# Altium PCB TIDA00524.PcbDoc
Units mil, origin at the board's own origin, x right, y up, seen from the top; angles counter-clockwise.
Board outline 2335 x 1723 mil, 2 copper layers (Top Layer, Bottom Layer), stack 62 mil thick; 54 components, 27 nets, 173 pads, 59 vias.
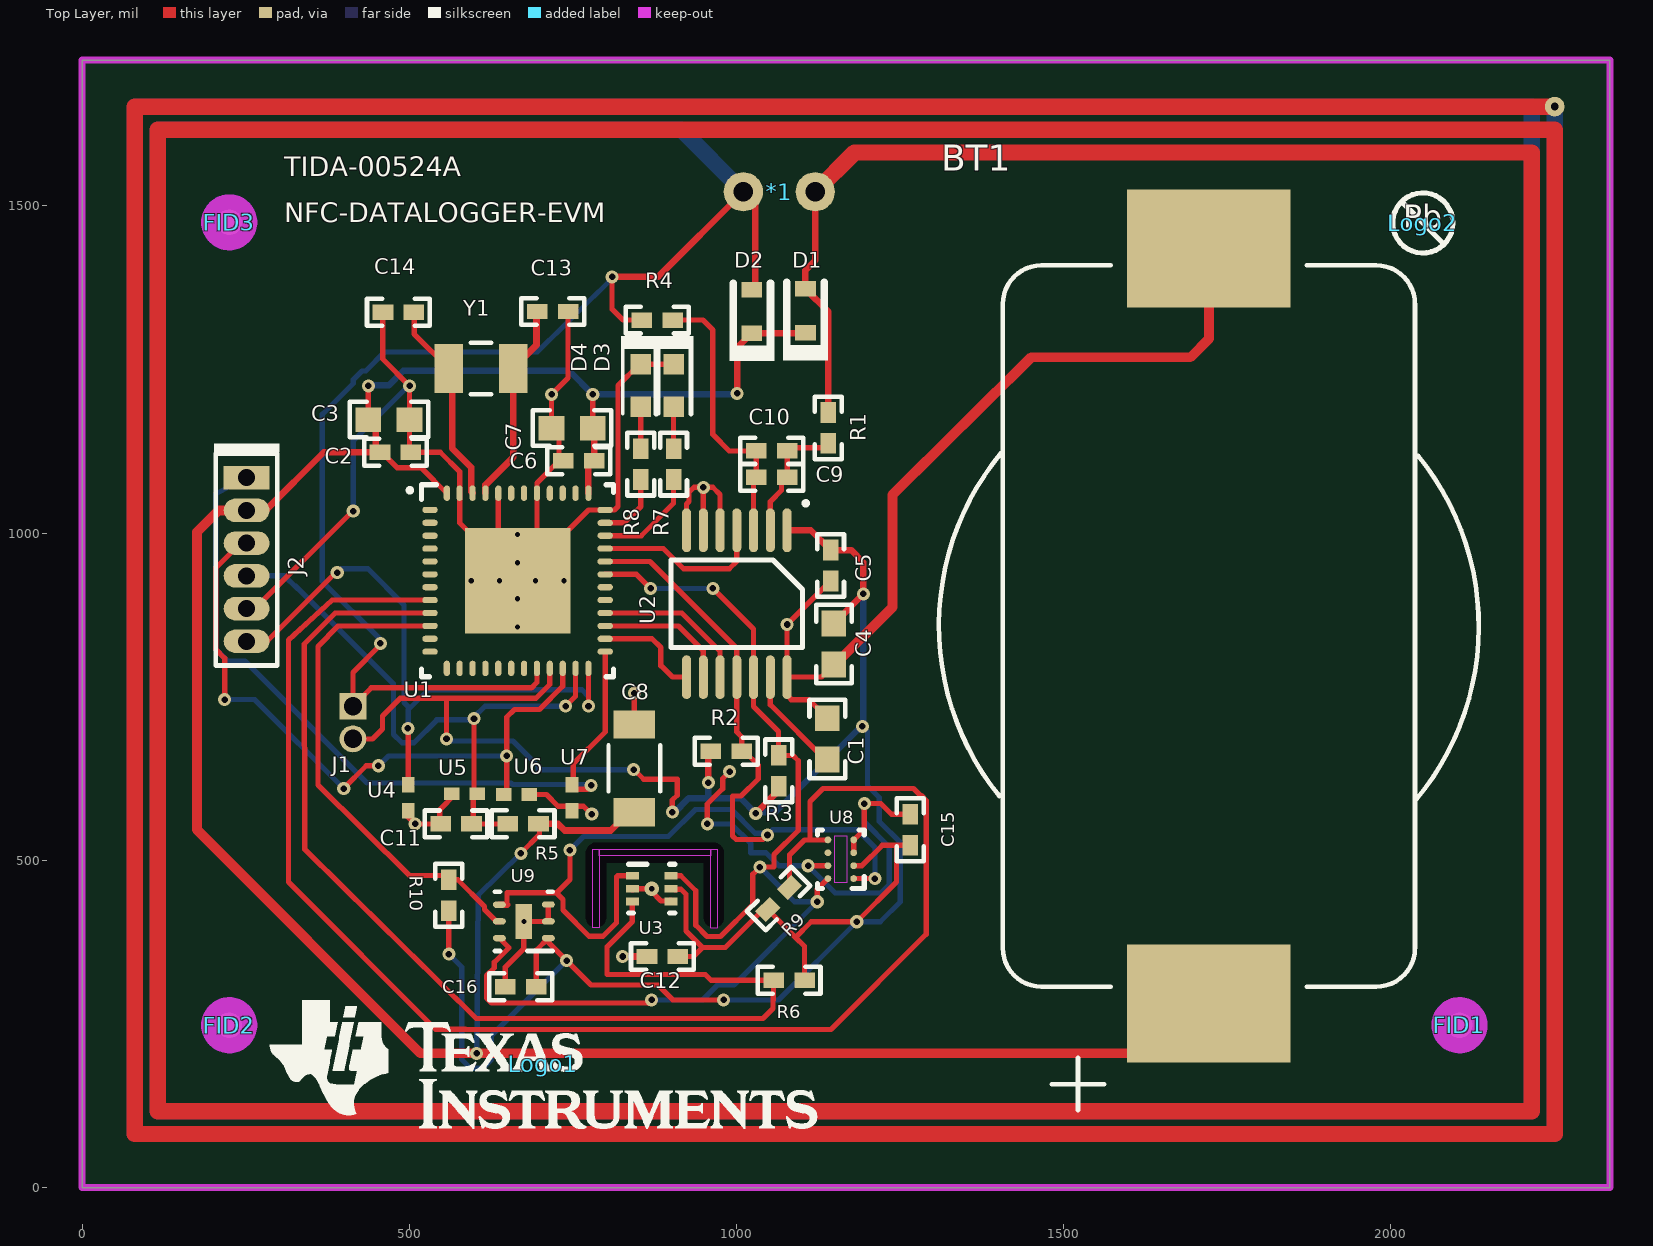
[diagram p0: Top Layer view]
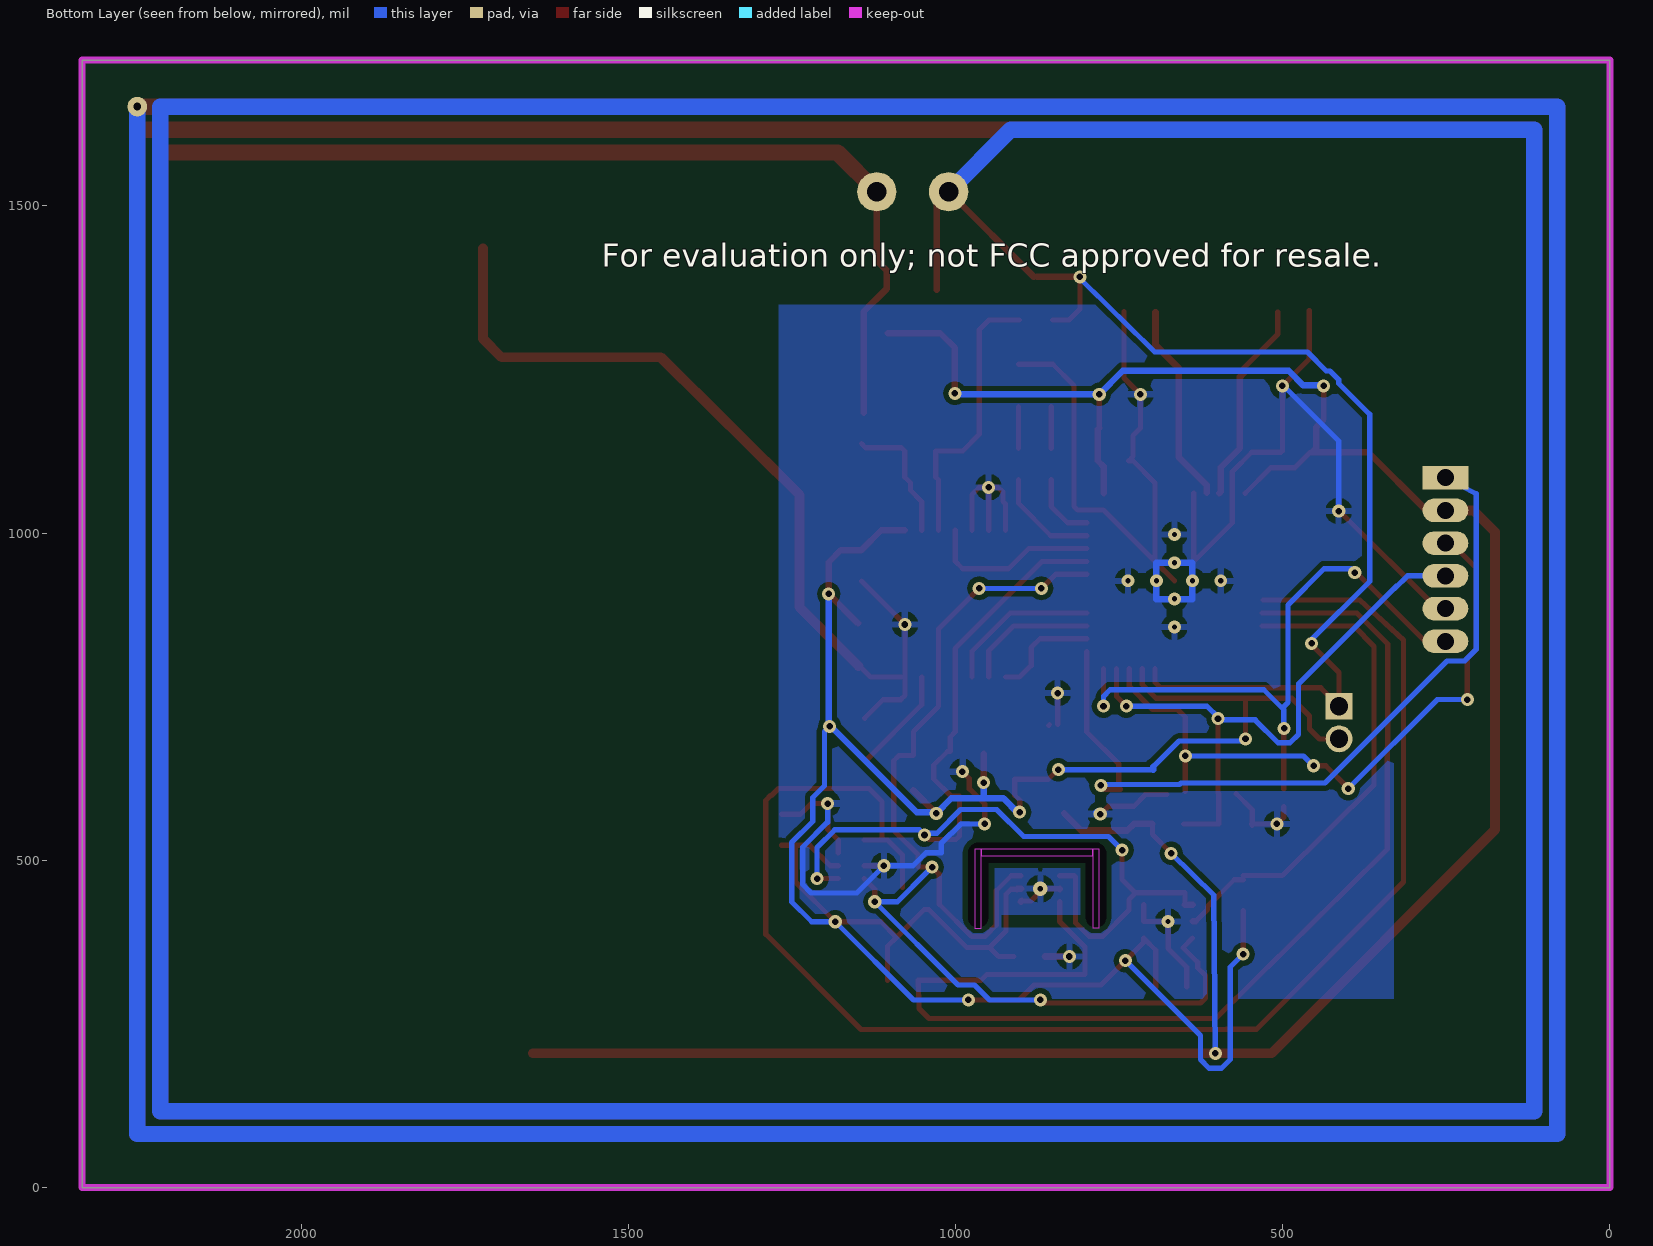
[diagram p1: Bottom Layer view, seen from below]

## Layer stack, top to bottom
Top Solder: solder mask 0.4, Solder Resist, Dk 3.5
Top Layer: signal copper 1.4
Dielectric1: core 59.2, FR-4, Dk 4.8
Bottom Layer: signal copper 1.4
Bottom Solder: solder mask 0.4, Solder Resist, Dk 3.5

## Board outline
0,0 2335,0 2335,1723 0,1723
cut-out: 790.55,506.69 790.55,516.69 960.55,516.69 960.55,506.69
cut-out: 960.55,516.55 970.55,516.55 970.55,396.55 960.55,396.55
cut-out: 780.55,516.69 790.55,516.69 790.55,396.69 780.55,396.69

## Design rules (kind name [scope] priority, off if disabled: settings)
AcuteAngle [All] p1: minimum=4.50000000000000E+0001 checktracksonly=FALSE
AssemblyTestPointUsage [All] p1: valid=2
Clearance Clearance_Keepouts [((IsTrack Or IsArc) And Not InPoly) And IsFree and IsKeepOut vs ((IsTrack Or IsArc) And Not InPoly) And IsFree and IsKeepOut] p1: gap=0
Clearance Clearance_BoardEdge_MountingHoles [OnCopper and InComponentClass('Mounting Holes') vs IsKeepOut] p2: gap=40
Clearance Clearance_BoardEdge_Poly [OnCopper and InPoly vs IsKeepOut] p3: gap=25
Clearance Clearance_BoardEdge [OnCopper and Not InComponentClass('Logo') and not InComponentClass('FiducialMark') and not InRegion(1000,500,4000,800) and Not IsKeepout and Not InComponent('*') vs IsKeepOut] p4: gap=5
Clearance Clearance_Poly [InPolygon] p5: gap=8
Clearance [All and not HasFootprint('PCBComponent_1') vs All and isFill and not HasFootprint('YPA0008AGAE')] p6: gap=7
ComponentClearance ComponentClearance_MountingHoles_FiducialMarks [InComponentClass('Mounting Holes') vs InComponentClass('FiducialMark')] p1: gap=50 collisioncheckmode=3 verticalgap=10 showdistances=FALSE
ComponentClearance ComponentClearance_Shunt [InComponentClass('Header') vs InComponentClass('Shunt')] p2: gap=0 collisioncheckmode=3 verticalgap=0 showdistances=FALSE
ComponentClearance ComponentClearance_Logo [InComponentClass('Logo')] p3: gap=50 collisioncheckmode=3 verticalgap=10 showdistances=FALSE
ComponentClearance ComponentClearance_ScrewToNut [(HasFootprint('NY PMS 440 0025 PH')) vs (HasFootprint('Keystone_1902C'))] p4: gap=5 collisioncheckmode=3 verticalgap=10 showdistances=FALSE
ComponentClearance ComponentClearance_MountingHoles [InComponentClass('Mounting Holes')] p5: gap=250 collisioncheckmode=3 verticalgap=100000 showdistances=FALSE
ComponentClearance ComponentClearance_SmallPassives [HasFootprint('0201*') or HasFootprint('0402*') or HasFootprint('0508') or HasFootprint('0603*') or HasFootprint('0612') or HasFootprint('0805*') or HasFootprint('0815*') or HasFootprint('0830*') or HasFootprint('1206*') or HasFootprint('1210*') or HasFootprint('1808*') or HasFootprint('1812*') or HasFootprint('1825*') or HasFootprint('2010*') or HasFootprint('2220*') or HasFootprint('2225*') or HasFootprint('2512*') or HasFootprint('2728*') or HasFootprint('3518*') vs HasFootprint('0201*') or HasFootprint('0402*') or HasFootprint('0508') or HasFootprint('0603*') or HasFootprint('0612') or HasFootprint('0805*') or HasFootprint('0815*') or HasFootprint('0830*') or HasFootprint('1206*') or HasFootprint('1210*') or HasFootprint('1808*') or HasFootprint('1812*') or HasFootprint('1825*') or HasFootprint('2010*') or HasFootprint('2220*') or HasFootprint('2225*') or HasFootprint('2512*') or HasFootprint('2728*') or HasFootprint('3518*')] p6: gap=10 collisioncheckmode=3 verticalgap=10 showdistances=FALSE
ComponentClearance ComponentClearance_THtoSMT [IsThruComponent and not HasFootprint('PCBComponent_1') vs IsSMTComponent and not HasFootprint('PCBComponent_1')] p7: gap=10 collisioncheckmode=3 verticalgap=10 showdistances=FALSE
ComponentClearance ComponentClearance_THtoTH [IsThruComponent and not HasFootprint('PCBComponent_1') vs IsThruComponent and not HasFootprint('PCBComponent_1')] p8: gap=10 collisioncheckmode=3 verticalgap=10 showdistances=FALSE
ComponentClearance [All and not HasFootprint('PCBComponent_1') vs All and not HasFootprint('PCBComponent_1')] p9: gap=10 collisioncheckmode=3 verticalgap=10 showdistances=FALSE
DiffPairsRouting [All] p1: maxlimit=100 minlimit=10 mostfreqgap=10 toplayer_minwidth=15 toplayer_maxwidth=15 toplayer_prefwidth=15 bottomlayer_minwidth=15 bottomlayer_maxwidth=15 bottomlayer_prefwidth=15 maxuncoupledlength=1000
FabricationTestPointUsage TestPointUsage [All] p1: valid=2 allowmultiple=FALSE
FabricationTestpoint Testpoint [All] p1: side=3 testpointundercomponent=TRUE minsize=40 maxsize=100 preferedsize=60 minholesize=0 maxholesize=40 preferedholesize=32 testpointgrid=1 allowsidetop=TRUE allowsidebottom=TRUE usegrid=TRUE gridtolerance=0.01
FanoutControl Fanout_LCC [IsLCC] p1: bgadir=Out bgaviamode=Centered fanoutstyle=Auto fanoutdirection=Alternating viagrid=1 // Fanout_LCC (Default Rule)
FanoutControl Fanout_BGA [IsBGA] p2: bgadir=Out bgaviamode=Centered fanoutstyle=Auto fanoutdirection=Alternating viagrid=1 // Fanout_BGA (Default Rule)
FanoutControl Fanout_Default [All] p4: bgadir=Out bgaviamode=Centered fanoutstyle=Auto fanoutdirection=Alternating viagrid=1 // Fanout_Default (Default Rule)
FanoutControl Fanout_Small [(CompPinCount < 5)] p5: bgadir=Out bgaviamode=Centered fanoutstyle=Auto fanoutdirection=OutThenIn viagrid=1 // Fanout_Small (Default Rule)
HoleSize [All] p1: absolutevalues=TRUE maxlimit=251 minlimit=7 maxpercent=80.000 minpercent=20.000
HoleToHoleClearance [All vs All And Not HasSlotHole] p1: gap=10 allowstackedmicrovias=TRUE
MinimumAnnularRing MinimumAnnularRing_ThermalPadVias [IsVia and InAnyComponent] p1: minimumring=5.91
MinimumAnnularRing [All] p2: minimumring=5
MinimumSolderMaskSliver MinimumSolderMaskSliver_Logo [InComponentClass('Logo') vs InComponentClass('Logo')] p1: minsoldermaskwidth=0.7
MinimumSolderMaskSliver [All] p2: minsoldermaskwidth=3.94
NetAntennae NetAntennae_1 [All and not HasFootprint('PCBComponent_1') Or OnTopLayer] p1: netantennaetolerance=1000
NetAntennae [All] p2: netantennaetolerance=0
PlaneConnect [All] p1: planeconnectstyle=Relief reliefexpansion=10 reliefentries=4 reliefconductorwidth=10 reliefairgap=10
PolygonConnect [All] p1: connectstyle=Relief reliefconductorwidth=10 reliefentries=4 polygonreliefangle="90 Angle" airgapwidth=10
RoutingVias ThermalPadVias [IsVia and InAnyComponent] p1: holewidth=7.87 width=19.68 viastyle="Through Hole" minholewidth=7 minwidth=19.68 maxholewidth=12.99 maxwidth=23.62
RoutingVias [All] p2: holewidth=16 width=34 viastyle="Through Hole" minholewidth=7 minwidth=19 maxholewidth=40 maxwidth=65
ShortCircuit ShortCircuit_1 [All and not HasFootprint ('YPA0008AGAE')] p1: allowed=TRUE
ShortCircuit [All] p2: allowed=FALSE
SilkToBoardRegionClearance [Not ((IsComment or IsDesignator) And (Hide <> 'False')) and not InRegion(1000,500,4000,800)] p1:
SilkToSilkClearance SilkToSilkClearance_Pb-FreeLogo [(HasFootprint('Pb-Free_Overlay_Medium') OR HasFootprint('Pb-Free_Overlay_Small')) vs (HasFootprint('Pb-Free_Overlay_Medium') OR HasFootprint('Pb-Free_Overlay_Small'))] p1: silktosilkclearance=0
SilkToSilkClearance [All] p2: silktosilkclearance=4
SilkToSolderMaskClearance SilkToSolderMaskslot [HasSlotHole vs InComponentClass('TIDA_00524')] p1: minsilkscreentomaskgap=0 clearancetoexposedcopper=TRUE
SilkToSolderMaskClearance SilkToComonentPadClearance [IsPad and InAnycomponent] p2: minsilkscreentomaskgap=3 clearancetoexposedcopper=TRUE
SilkToSolderMaskClearance "Silk to Solder Mask Opening" [All and not HasFootprint('PCBComponent_1')] p3: minsilkscreentomaskgap=3 clearancetoexposedcopper=FALSE
SolderMaskExpansion [All] p1: expansion=1.97
UnpouredPolygon [All] p1: allowunpoured=FALSE
Width [All] p1: maxlimit=100 minlimit=6 preferedwidth=10 checkconnectedcopper=TRUE
11 further rules are at their usual default settings.

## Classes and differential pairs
component class TIDA_00524: * BT1 C1 C2 C3 C4 C5 C6 C7 C8 C9 C10 C11 C12 C13 C14 C15 C16 D1 D2 D3 D4 J1 J2 R1 R2 R3 R4 R5 R6 R7 R8 R9 R10 U1 U2 U3 U4 U5 U6 U7 U8 U9 Y1
component class AssemblyNote: ZZ1 ZZ2 ZZ3 ZZ4
component class FiducialMark: FID1 FID2 FID3
component class TIDA00524_Hardware: FID1 FID2 FID3 Logo1 Logo2 Logo3 ZZ1 ZZ2 ZZ3 ZZ4
component class Logo: Logo1

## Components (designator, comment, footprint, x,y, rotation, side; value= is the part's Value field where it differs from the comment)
*1 "Antenna" PCBComponent_1 65.55,96.69 r0 top locked
BT1 "BA2032SM" BAT_BA2032SM 1722,858 r90 top
C1 "GRM188R71E474KA12D" 0603 1139,685.55 r90 top
C2 "GRM155R71C104KA88D" 0402 479,1123.55 r0 top
C3 "GRM188R71C105KA12D" 0603 469,1173.55 r0 top
C4 "GRM188R71C105KA12D" 0603 1149,830.55 r270 top
C5 "GRM155R71C104KA88D" 0402 1144,950.55 r270 top
C6 "GRM155R71C104KA88D" 0402 759,1110.55 r180 top
C7 "GRM188R71C105KA12D" 0603 749,1160.55 r180 top
C8 "C3216X5R1A107M160AC" 1206_190 844,640.55 r90 top
C9 "GRM1555C1H220FA01D" 0402 1054,1085.55 r180 top
C10 "GRM1555C1H180JA01D" 0402 1054,1125.55 r180 top
C11 "GRM155R71C102KA01D" 0402 571.55,555.69 r180 top
C12 "GRM155R71C103KA01D" 0402 887,353 r0 top
C13 "GRM1555C1H220FA01D" 0402 719.55,1338.69 r0 top
C14 "GRM1555C1H220FA01D" 0402 483.55,1337.69 r180 top
C15 "C1005X7R1E103K" 0402 1265.55,546.69 r90 top
C16 "885012205031" 0402 670.55,306.69 r180 top
D1 "CDBU0130L" SOD-523F 1105.55,1339.69 r90 top
D2 "CDBU0130L" SOD-523F 1023.55,1338.69 r90 top
D3 "SML-311DTT86" SML-31_Orange 904,1225.55 r270 top
D4 "SML-311UTT86" SML-31_Red 854,1225.55 r270 top
FID1 "Fiducial" Fiducial10-20 2105,248 r0 top
FID2 "Fiducial" Fiducial10-20 225,248 r0 top
FID3 "Fiducial" Fiducial10-20 225,1475 r0 top
J1 "GRPB021VWVN-RC" Sullins_GRPB021VWVN-RC 414,710.55 r270 top
J2 "851-43-006-10-001000" Mill-Max_851-XX-006-10-001000 251.55,959.69 r90 top
Logo1 "Texas Instruments" TI_Stacked_Overlay_Small 705,188 r0 top
Logo2 "Pb-Free Symbol" Pb-Free_Overlay_Small 2049,1474 r0 top
Logo3 "FCC disclaimer" FCC_disclaimer 1205.2,3026.69 r180 bottom
R1 "CRCW04020000Z0ED" 0402 1140.55,1160.69 r90 top
R2 "CRCW04024K75FKED" 0402 984.55,666.69 r180 top
R3 "CRCW04024K75FKED" 0402 1064.55,636.69 r270 top
R4 "CRCW04020000Z0ED" 0402 879,1325.55 r180 top
R5 "CRCW040247K5FKED" 0402 674,556 r0 top
R6 "CRCW040210K0FKED" 0402 1080.55,316.69 r0 top
R7 "CRCW04021K00FKED" 0402 904,1105.55 r270 top
R8 "CRCW04021K00FKED" 0402 854,1105.55 r270 top
R9 "CRCW040210K0FKED" 0402 1064.55,441.69 r45 top
R10 "CRCW040210K0JNED" 0402 560.55,446.69 r270 top
U1 "MSP430FR5969IRGZ" RGZ0048B 665.69,927.16 r0 top
U2 "RF430CL331HIPWR" PW0014A_N 1000.69,892.16 r270 top
U3 "TMP112AIDRL" DRL0006A 870.55,456.69 r0 top
U4 "TPD1E10B06DPYR" DPY0002A 498.55,595.69 r270 top
U5 "TPD1E10B06DPYR" DPY0002A 584.55,601.69 r180 top
U6 "TPD1E10B06DPYR" DPY0002A 664,600.55 r0 top
U7 "TPD1E10B06DPYR" DPY0002A 749,595.55 r270 top
U8 "HDC1000YPAR" YPA0008AGAE 1159.55,501.69 r180 top
U9 "OPT3001DNP" DNP0006A 675.22,406.69 r180 top
Y1 "ABS07-32.768KHZ-9-T" XTAL_ABS07 609.55,1251.69 r0 top
ZZ1 "These assemblies must use No Clean paste." AssemblyNote 185,3829.11 r0 top
ZZ2 "These assemblies are ESD sensitive, ESD precautions shall be observed." AssemblyNote 185,3740.56 r0 top
ZZ3 "These assemblies must be clean and free from flux and all contaminants. Use of no clean flux is not acceptable." AssemblyNote 185,3652 r0 top
ZZ4 "These assemblies must comply with workmanship standards IPC-A-610 Class 2, unless otherwise specified." AssemblyNote 185,3550 r0 top

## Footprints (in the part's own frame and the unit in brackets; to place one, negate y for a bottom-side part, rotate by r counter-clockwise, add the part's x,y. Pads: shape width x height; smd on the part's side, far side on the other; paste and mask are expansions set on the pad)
0402 [mm] "0402 from SM-752 data"
  rect 0.8x0.6 smd: 1(-0.6,0) 2(0.6,0)
  silkscreen extent -1.22,-0.52 1.22,0.52, body extent -0.55,-0.3 0.55,0.3, height 0.6
0603 [mm] "0603 from SM-752 data"
  rect 1x0.95 smd: 1(-0.8,0) 2(0.8,0)
  silkscreen extent -1.52,-0.69 1.52,0.69, body extent -0.87,-0.47 0.87,0.47, height 0.85
1206_190 [mm] "1206_190"
  rect 1.1x1.6 smd: 1(-1.7,0) 2(1.7,0)
  silkscreen extent -0.9,-1 0.9,1, body extent -1.75,-0.95 1.75,0.95, height 1.9
AssemblyNote [mil] "Assembly Note"
BAT_BA2032SM [mil] "Memory Protection Devices CR-2032 battery holder"
  rect 180x250 smd: 1(-577,0) 2(577,0)
  silkscreen extent -740,-412 551,412, body extent -630,-315 630,315, height 264
DNP0006A [mm] "DFN-6 2x2mm"
  oval 0.5x0.25 smd: 1(-0.95,0.65) 2(-0.95,0) 3(-0.95,-0.655) 4(0.95,-0.65) 5(0.95,0) 6(0.95,0.65)
  rect 0.65x1.35 smd paste-0.5: 7(0,0)
  silkscreen extent -1.12,-1.15 1.12,1.15, body extent -1.05,-1.05 1.05,1.05, height 0.66
DPY0002A [mm] "R-PX2SON-N2"
  rect 0.6x0.5 smd: 1(-0.5,0) 2(0.5,0)
  body extent -0.55,-0.35 0.55,0.35, height 0.4
DRL0006A [mm] "SOTFL, 6-Flat Leads, Body 1.2x1.6x0.6mm, Pitch 0.5mm, TI recommended"
  rect 0.5x0.3 smd: 1(-0.75,0.5) 2(-0.75,0) 3(-0.75,-0.5) 4(0.75,-0.5) 5(0.75,0) 6(0.75,0.5)
  silkscreen extent -0.9,-0.95 0.9,0.95, body extent -0.85,-0.85 0.85,0.85, height 0.62
FCC_disclaimer [mil]
Fiducial10-20 [mm]
  round 1 smd mask+0.5: 1(0,0)
  Top Layer keep-out circle w1.178: c0,0 r0.5
Mill-Max_851-XX-006-10-001000 [mil] "Mill-Max"
  rect 36x70 hole 26: 1(125,0)
  oval 36x70 hole 26: 2(75,0) 3(25,0) 4(-25,0) 5(-75,0) 6(-125,0)
  silkscreen extent -162,-50 177,50, body extent -160,-45 160,45, height 162
Pb-Free_Overlay_Small [mil]
  silkscreen extent -46,-46 46,46
PCBComponent_1 [mil]
  round 60 hole 30: 0(1055,1425) 1(945,1425)
  Top Layer lines w25: 50,20 50,1520 2185,1520 2185,-15 15,-15 15,1555 2185,1555 ; 55,20 2150,20 2150,1485 1115,1485 1055,1425
  Bottom Layer lines w25: 945,1425 850,1520 835,1520 50,1520 50,20 2150,20 2150,1555 15,1555 15,-15 2185,-15 2185,1555
PW0014A_N [mm] "TSOP, 14-Leads, Body 5x4.4mm, Pitch 0.65mm, IPC Medium Density"
  oval 1.7x0.35 smd: 1(-2.85,1.95) 2(-2.85,1.3) 3(-2.85,0.65) 4(-2.85,0) 5(-2.85,-0.65) 6(-2.85,-1.3) 7(-2.85,-1.95) 8(2.85,-1.95) 9(2.85,-1.3) 10(2.85,-0.65) 11(2.85,0) 12(2.85,0.65) 13(2.85,1.3) 14(2.85,1.95)
  silkscreen extent -1.7,-2.55 1.7,2.55, body extent -3.21,-2.5 3.21,2.5, height 0.98
RGZ0048B [mm] "QFN, 48-Leads, Body 7x7mm, Pitch 0.5mm, Thermal Pad 5.15x5.15mm, TI Recommended"
  oval 0.6x0.24 smd: 1(-3.4,2.75) 2(-3.4,2.25) 3(-3.4,1.75) 4(-3.4,1.25) 5(-3.4,0.75) 6(-3.4,0.25) 7(-3.4,-0.25) 8(-3.4,-0.75) 9(-3.4,-1.25) 10(-3.4,-1.75) 11(-3.4,-2.25) 12(-3.4,-2.75) 25(3.4,-2.75) 26(3.4,-2.25) 27(3.4,-1.75) 28(3.4,-1.25) 29(3.4,-0.75) 30(3.4,-0.25) 31(3.4,0.25) 32(3.4,0.75) 33(3.4,1.25) 34(3.4,1.75) 35(3.4,2.25) 36(3.4,2.75)
  oval 0.24x0.6 smd: 13(-2.75,-3.4) 14(-2.25,-3.4) 15(-1.75,-3.4) 16(-1.25,-3.4) 17(-0.75,-3.4) 18(-0.25,-3.4) 19(0.25,-3.4) 20(0.75,-3.4) 21(1.25,-3.4) 22(1.75,-3.4) 23(2.25,-3.4) 24(2.75,-3.4) 37(2.75,3.4) 38(2.25,3.4) 39(1.75,3.4) 40(1.25,3.4) 41(0.75,3.4) 42(0.25,3.4) 43(-0.25,3.4) 44(-0.75,3.4) 45(-1.25,3.4) 46(-1.75,3.4) 47(-2.25,3.4) 48(-2.75,3.4)
  rect 4.1x4.1 smd paste-2.575: 49(0,0)
  silkscreen extent -3.72,-3.72 3.72,3.72, body extent -3.57,-3.58 3.58,3.57, height 1.01
SML-31_Orange [mm] "Rohm"
  rect 0.8x0.8 smd: 1(-0.825,0) 2(0.825,0)
  silkscreen extent -1.93,-0.77 1.1,0.77, body extent -0.85,-0.45 0.85,0.45, height 0.91
SML-31_Red [mm] "Rohm"
  rect 0.8x0.8 smd: 1(-0.825,0) 2(0.825,0)
  silkscreen extent -1.93,-0.76 1.1,0.76, body extent -0.85,-0.45 0.85,0.45, height 0.91
SOD-523F [mm] "COMCHIP"
  rect 0.6x0.8 smd paste-0.05: 1(-0.85,0) 2(0.85,0)
  silkscreen extent -1.92,-0.88 1.1,0.87, body extent -0.9,-0.5 0.9,0.5, height 0.85
Sullins_GRPB021VWVN-RC [mil] "Sullins"
  rect 41x41 hole 28: 1(-25,0)
  round 41 hole 28: 2(25,0)
  body extent -50,-42 50,42, height 157
TI_Stacked_Overlay_Small [mil]
  silkscreen extent -418,-98 418,98
XTAL_ABS07 [mm] "ABRACON"
  rect 1.1x1.9 smd: 1(-1.25,0) 2(1.25,0)
  silkscreen extent -0.4,-1 0.4,1, body extent -1.65,-0.8 1.65,0.8, height 0.9
YPA0008AGAE [mm] "BGA, 8-Leads, Body 2.04x1.59mm, Pitch 0.5mm"
  round 0.263 smd paste-0.14: A1(-0.5,0.75) A2(0.5,0.75) B1(-0.5,0.25) B2(0.5,0.25) C1(-0.5,-0.25) C2(0.5,-0.25) D1(-0.5,-0.75) D2(0.5,-0.75)
  Top Layer keep-out region: -0.25,-0.9 0.25,-0.9 0.25,0.9 -0.25,0.9
  silkscreen extent -0.91,-1.14 0.91,1.14, body extent -0.81,-1.04 0.81,1.04, height 0.68

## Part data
*1: library part Component_1
BT1: "Battery Holder,xx 2032 series, 20mm Dia, SMT"
C1: "CAP, CERM, 0.47 µF, 25 V, +/- 10%, X7R, 0603"
C2 C5 C6: "CAP, CERM, 0.1 µF, 16 V, +/- 10%, X7R, 0402"
C3 C4 C7: "CAP, CERM, 1 µF, 16 V, +/- 10%, X7R, 0603"
C8: "CAP, CERM, 100 µF, 10 V, +/- 20%, X5R, 1206_190"
C9 C13 C14: "CAP, CERM, 22 pF, 50 V, +/- 1%, C0G/NP0, 0402"
C10: "CAP, CERM, 18 pF, 50 V, +/- 5%, C0G/NP0, 0402"
C11: "CAP, CERM, 1000 pF, 16 V, +/- 10%, X7R, 0402"
C12 C16: "CAP, CERM, 0.01 µF, 16 V, +/- 10%, X7R, 0402"
C15: "CAP, CERM, 0.01 µF, 25 V, +/- 10%, X7R, 0402"
D1 D2: "Diode, Schottky, 35 V, 0.1 A, SOD-523F"
D3: "LED, Orange, SMD"
D4: "LED, Red, SMD"
FID1 FID2 FID3: "Fiducial mark.  There is nothing to buy or mount."
J1: "Header male, 2x1, 50mil, TH"
J2: "Receptacle, 6x1, 50mil, TH"
Logo1: library part TI_Logo, "Texas Instrument Corporate Signature"
Logo2: library part Pb-Free
Logo3: library part FCC_disclaimer, "FCC_disclaimer"
R1 R4: "RES, 0, 5%, 0.063 W, 0402"
R2 R3: "RES, 4.75 k, 1%, 0.063 W, 0402"
R5: "RES, 47.5 k, 1%, 0.063 W, 0402"
R6 R9: "RES, 10.0 k, 1%, 0.063 W, 0402"
R7 R8: "RES, 1.00 k, 1%, 0.063 W, 0402"
R10: "RES, 10 k, 5%, 0.063 W, 0402"
U1: "Mixed Signal Microcontroller, RGZ0048B"
U2: "NFC Type 4B Dynamic Dual Interface Transponder, PW0014A"
U3: "High-Accuracy, Low-Power, Digital Temperature Sensor With SMBus(TM)/Two-Wire Serial Interface, DRL0006A"
U4 U5 U6 U7: "ESD in 0402 Package with 10 pF Capacitance and 6 V Breakdown, 1 Channel, -40 to +125 degC, 2-pin X2SON (DPY), Green (RoHS & no Sb/Br)"
U8: "HDC1000 Low power integrated humidity and temperature Sensor, YPA0008AGAE"
U9: "Ambient Light Sensor, DNP0006A"
Y1: "CRYSTAL, 32.768KHZ, 9PF, SMD"
ZZ1 ZZ2 ZZ3 ZZ4: library part AssemblyNote

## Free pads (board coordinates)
  round 10 hole 31 slot 130 at 90 deg unplated mask+0: 0(965.55,462) 1(785.5,462)
  round 30 hole 12: 0(2250.55,1651.69)
  round 10 hole 31 slot 210 at 0 deg unplated mask+0: 2(875.5,511.5)

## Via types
v1: diameter 20, hole 10, Top Layer to Bottom Layer, tented both sides, 49 vias
v2: diameter 19.68, hole 7.87, Top Layer to Bottom Layer, 9 vias
v3: diameter 22, hole 8, Top Layer to Bottom Layer, 1 vias

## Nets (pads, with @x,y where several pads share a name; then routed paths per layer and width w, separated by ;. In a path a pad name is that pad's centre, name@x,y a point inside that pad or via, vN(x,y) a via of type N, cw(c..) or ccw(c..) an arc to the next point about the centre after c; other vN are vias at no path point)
A0_RXD: J2.1 U1.25 U7.1 | length 1226
  Top Layer w8: U7.1@748.55,608.69 772.14,608.69 v1(778,614.55) ; U7.1@750.55,608.93 750.55,647.1 799.55,696.1 799.55,735.55 U1.25
  Bottom Layer w8: J2.1@235.55,1078.06 J2.1@235.55,1091.32 ; J2.1 204.55,1060.32 204.55,822.26 222.12,804.69 248.9,804.69 435.42,618.16 655.63,618.16 658.1,615.69 v1@778.55,615.69
A0_TXD: J2.6 U1.24 U4.1 | length 954.5
  Top Layer w8: J2.6 282.55,834.69 v1@388.55,940.69 ; U4.1@498.55,609.08 v1@498.55,701.69 ; v1(774,735.55) U1.24
  Bottom Layer w8: v1@390.55,940.69 395.55,945.69 436.55,945.69 492,890.24 492,741.24 500.55,732.69 ; v1@498.55,701.69 498.55,730.1 529,760.55 764,760.55 774,750.55 v1(774,735.55)
  other v1: 498,701.55 390,939.55
B0_SCL: R2.1 U1.32 U2.11 U3.1 U8.A1 U9.4 | length 1652.7
  Top Layer w8: 649.55,432.28 649.55,450.27 724.91,450.27 ; v1(745.55,515.69) 745.55,470.91 724.91,450.27 ; U1.32 867.86,956.69 1000.69,823.86 U2.11 1000.69,696.05 1008.17,688.57 R2.1 1012.05,666.69 1033.55,645.19 1033.55,624.69 1007.24,598.37 994.24,598.37 994.24,537.16 999.71,531.69 1040.55,531.69 v1(1047.55,538.69) ; U3.1 818.2,476.37 816.59,474.77 816.59,404.53 795.88,383.82 775.22,383.82 735,424.03 735,440.19 724.91,450.27 ; U8.A1 v1(1211.7,472.13)
  Top Layer w10: U9.4 649.55,432.28
  Bottom Layer w8: v1(745.55,515.69) 766.21,536.35 895.92,536.35 937.25,577.69 992.44,577.69 1028.69,541.44 v1@1040.55,541.44 ; v1@1043.55,534.69 v1(1047.55,538.69) 1055.55,546.69 1184.55,546.69 1211.7,519.54 v1(1211.7,472.13)
B0_SDA: R3.1 U1.31 U2.12 U3.6 U8.A2 U9.6 | length 1808
  Top Layer w8: U9.6 652.45,366.47 630.05,344.07 630.05,335.58 618.31,323.83 618.31,289.55 625.85,282 v1@865.87,282 ; U1.31 847.54,937 v1(869,915.55) ; U3.6 915,476.37 937.99,453.38 937.99,400.9 955.22,383.67 975.88,383.67 1025,432.79 1025,478.55 v1(1036,489.55) ; v1(964,915.55) 1026.28,853.26 U2.12 1026.28,734.96 1064.55,696.69 R3.1 1086.43,660.31 1094.55,652.19 1094.55,545.69 ; v1@1036.14,489.69 1057.55,489.69 1057.55,508.73 1094.51,545.69 ; v1(1123.55,436.69) v1@1123.71,436.85 ; v1@1125.71,438.85 v1@1123.71,436.85 ; U8.A2 1123.71,456 v1@1123.71,436.85
  Top Layer w10: v1@865.87,282 v1(870.55,286.69) ; v1(1036,489.55) v1@1036.14,489.69
  Bottom Layer w8: v1(869,915.55) v1(964,915.55) ; v1(870.55,286.69) 948.2,286.69 971.08,309.56 996.42,309.56 v1(1123.55,436.69) 1088.86,436.69 v1@1042.7,482.84
GND: BT1.2 C1.2 C2.2 C3.2 C4.2 C5.2 C6.2 C7.2 C8.2 C11.2 C12.1 C13.2 C14.2 C15.2 C16.2 D3.1 D4.1 J2.5 U1.36 U1.41 U1.44 U1.47 U1.49 U2.5 U2.6 U2.7 U2.14 U3.2 U3.4 U4.2 U5.2 U6.2 U7.2 U8.B2 U8.C1 U8.D1 U9.2 U9.3 U9.7 | length 5097.2
  Top Layer w8: J2.5 264.55,884.69 v1@412.55,1032.69 ; C14.2@459.55,1339.69 459.55,1265.99 v1(500.49,1225.04) C3.2 500.49,1125.67 C2.2 ; U4.2@498.55,582.3 498.55,565.69 v1@509.55,554.69 ; C2.2@503.55,1123.69 547.55,1123.69 577.11,1094.13 U1.47 577.11,1015.74 636.16,956.69 U1.44 ; v1@510.55,555.69 C11.2@546.55,555.69 ; C11.2@546.55,553.69 C11.2@546.55,555.69 ; C11.2 C11.2@546.55,555.69 ; U5.2@571.16,601.69 546.55,577.08 C11.2@546.55,555.69 ; C16.2 646.93,337.08 675.22,365.37 v2(675.22,406.69) U9.2 U9.3 ; U1.49 U1.49@695.22,956.69 ; U6.2@677.38,600.55 709.69,600.55 727.55,582.69 766.55,582.69 v1@778.55,570.69 ; C13.2@742.55,1338.69 742.55,1237.09 v1(717.5,1212.04) C7.2 729,1149.05 729,1116.93 C6.2 729,1110.55 695.22,1076.77 U1.41 U1.49@695.22,956.69 ; U3.2 v3(870.55,456.69) ; C8.2 v1(844,755.55) ; C8.2@856.49,707.48 C8.2@857.78,706.19 ; v3@870.55,452.27 884.9,437.91 U3.4@899.17,437.91 ; D3.1 D4.1 851.48,1258.03 819,1225.55 819,1040.55 813.88,1035.43 U1.36 773.96,1035.43 U1.49@695.22,956.69 ; U2.7 923.92,1044.45 927.68,1048.21 927.68,1062.61 935.11,1070.04 v1(949.51,1070.04) ; U2.6 v1(949.51,1070.04) ; v1(955.55,555.69) 955.55,585.99 979.07,609.51 979.07,625.21 v1(989.55,635.69) ; U2.5 975.1,1058.84 963.91,1070.04 v1(949.51,1070.04) ; v1(1109.55,491.69) U8.B2@1139.71,491.69 ; C1.2 1110.49,745.55 1084,745.55 1077.46,752.08 U2.14 ; C5.2 v1(1077.46,860.39) U2.14 ; C4.2@1147.59,797.65 1129.9,779.96 U2.14 ; U8.C1 U8.D1 1195.55,547.53 v1(1195.55,586.69) ; v1@1197.61,586.69 1220.55,586.69 1236.93,570.31 C15.2
  Top Layer w10: v1(826,353) C12.1 ; U3.2@841.02,455.78 U3.2 ; U3.4@899.17,437.91 U3.4
  Top Layer w15: C4.2@1148.55,796.69 1238.55,886.69 1238.55,1058.69 1450.55,1268.69 1555.69,1268.69 1693.69,1268.69 1722,1297 BT1.2
  Bottom Layer w8: v1(414.55,1033.69) 414.55,1140.69 v1@500.55,1226.69 ; v1@784,575.55 v1@785.86,573.69 ; v1(955.55,555.69) 991.81,555.69 1022.06,525.44 1022.06,511.55 1045.11,511.55 1064.97,491.69 v1(1109.55,491.69) 1151.11,450.13 1220.81,450.13 1233.7,463.02 1233.7,520.17 1195.55,558.32 v1(1195.55,586.69)
  Bottom Layer w10: v2@662.52,954.72 638.13,954.72 v2(638.13,927.16) 638.13,899.11 638.25,898.99 693.25,898.99 v2(693.25,927.16) 693.25,954.72 v2(665.69,954.72)
  other v1: 509,555.55 779,570.55
  other v2: 665.69,856.3 665.69,899.6 594.83,927.16 736.56,927.16 665.69,998.03
HDC_DRDY: R9.2 U1.8 U8.D2 | length 2309
  Top Layer w8: U1.8@529.87,897.67 382.49,897.67 315.55,836.69 315.55,821.66 315.55,466.69 540.55,241.69 585.55,241.69 1144.58,241.54 1290.24,387.19 1290.24,591.39 1282.69,598.93 ; R9.2 1081.25,508.39 1104.08,531.22 1112.55,531.22 ; U8.D2 1112.55,531.22 ; 1281.31,598.93 1270.55,609.69 1132.55,609.69 1112.55,589.69 1112.55,531.22
Net*1_2: D1.2 R1.2 | length 358.1
  Top Layer w10: 1120.55,1521.69 1120.55,1416.69 1105.55,1401.69 D1.2 1140.55,1338.15 R1.2
NetC1_1: C1.1 U2.13 | length 164
  Top Layer w8: U2.13 1051.87,737.67 1135.49,654.05 C1.1
NetC9_1: C9.1 C10.1 R1.1 U2.2 | length 202.9
  Top Layer w8: U2.2 1051.87,1048.42 1069,1065.55 1069,1076.93 C9.1 C10.1 1082.62,1130.55 1137.62,1130.55 R1.1@1144,1136.93
NetC9_2: C9.2 C10.2 R4.1 U2.3 | length 427.2
  Top Layer w8: R4.1 949,1325.55 964,1310.55 964,1275.55 964,1150.55 989,1125.55 C10.2 C9.2 1026.28,1081.45 U2.3
NetC13_1: C13.1 U1.45 Y1.2 | length 308.3
  Top Layer w10: U1.45@616.55,1061.69 616.55,1073.56 658.76,1115.77 Y1.2 694.55,1287.48 C13.1@694.55,1337.69
NetC14_1: C14.1 U1.46 Y1.1 | length 307
  Top Layer w8: C14.1@507.55,1337.69 507.55,1304.48 Y1.1
  Top Layer w10: Y1.1@559.55,1244.69 565.55,1238.69 565.55,1129.73 594.83,1100.45 594.83,1062.98 U1.46
NetD3_2: D3.2 R7.1 | length 63.9
  Top Layer w8: R7.1 D3.2
NetD4_2: D4.2 R8.1 | length 63.9
  Top Layer w8: R8.1 D4.2
NetR7_2: R7.2 U1.34 | length 161.3
  Top Layer w8: U1.34 854.51,996.06 904,1045.55 R7.2
NetR8_2: R8.2 U1.35 | length 106.1
  Top Layer w8: U1.35 829.2,1015.74 854,1040.55 R8.2
OPT_INT: R10.1 U1.10 U9.5 | length 759.4
  Top Layer w8: U1.10 391.12,858.26 360.55,826.69 360.55,615.12 500.55,476.69 R10.1@560.55,476.69 ; R10.1 574.2,470.31 615.1,429.41 615.1,424.91 U9.5@633.32,406.69
  Top Layer w10: U9.5@633.32,406.69 U9.5
P2.5: *1.1 D2.2 J1.1 pad.0@2250.55,1651.69 R4.2 U1.20 | length 1819.9
  Top Layer w8: v1@456.55,829.69 414,787.14 J1.1 442,763.55 686.74,763.55 695.22,772.02 U1.20 ; v1(810,1391.55) 810,1342.24 826.69,1325.55 R4.2@851.41,1325.55
  Top Layer w10: v1(810,1391.55) 875.41,1391.55 ; 880.41,1391.55 *1.1 ; D2.2@1028.55,1372.15 *1.1@1028.55,1503.69
  Bottom Layer w8: v1@456,837.33 367.12,926.2 367.12,1181.54 414.63,1229.04 414.63,1234.52 428.03,1247.92 433.51,1247.92 462.28,1276.69 695.55,1276.69 v1@809.55,1388.69
  other v1: 456,831.55
P2.6: C4.1 C5.1 C12.2 C15.1 C16.1 J1.2 R2.2 R3.2 R6.2 R9.1 R10.2 U1.21 U2.1 U3.5 U8.B1 U9.1 | length 4059.3
  Top Layer w8: J1.2 444,685.55 459,700.55 459,720.55 486,747.55 693.37,747.55 714.9,769.08 U1.21 ; v1(557,685.55) 557,746.1 ; v1(560.55,356.69) R10.2 ; C16.1 694.17,362.65 U9.1 712.62,374.62 v1(740.55,346.69) 777.68,309.56 880.02,309.56 902.9,286.69 v1(980.55,286.69) ; v1@844.55,637.69 858.38,623.86 909.55,623.86 909.55,599.48 902.07,592 v1(902.07,573.62) ; U3.5@906.58,455.78 915.25,455.78 922.79,448.24 922.79,392.23 948.23,366.8 ; C12.2 934.43,353 948.23,366.8 ; R6.2 1104.17,368.66 1090.55,382.28 ; U8.B1 1191.82,491.85 1223.04,523.07 1244.55,523.07 ; C15.1 1244.55,523.07 ; 948.23,366.8 982.87,366.8 1041.06,424.99 R9.1 1090.55,382.28 ; 1090.55,382.28 1114.33,406.07 v1(1183.93,406.07) 1244.55,466.69 1244.55,523.07
  Top Layer w10: U3.5 905.67,456.69 U3.5@906.58,455.78 ; v1(957.07,618.62) R2.2@957.07,662.83 ; v1(1029.55,571.69) R3.2@1064.55,606.69 ; U2.1 1113.8,1004.37 C5.1 1175.38,974.17 1194,955.55 v1(1194,907.04) C4.1
  Bottom Layer w8: v1@560.12,682.42 658.47,682.42 698.28,642.61 ; v1(560.55,356.69) 580.21,337.03 580.21,195.57 593.61,182.17 612.56,182.17 625.96,195.57 625.96,232.1 v1(740.55,346.69) ; 698.28,638.55 v1(843,638.55) ; v1(980.55,286.69) 1064.55,286.69 v1(1183.93,406.07) 1219.93,406.07 1250.57,436.71 1250.57,527.16 1218.42,559.31 1218.42,596.16 1200.55,614.04 1200.55,696.69 v1(1192.55,704.69)
  Bottom Layer w10: 698.28,638.55 698.28,642.61 ; v1@904,571.69 927,594.69 1006.55,594.69 v1(1029.55,571.69) ; 957.07,594.69 v1(957.07,618.62) ; v1@1029.55,573.62 1059.55,573.62 1194,708.07 v1(1194,907.04)
RF430_CS: U1.27 U2.9 | length 205.9
  Top Layer w8: U1.27 911.28,858.26 949.51,820.04 U2.9
RF430_IRQ: U1.26 U2.8 | length 165
  Top Layer w8: U1.26 870.97,838.58 884.55,825 884.55,797.48 884.81,797.74 902.59,779.96 U2.8
RF430_RST: U1.33 U2.4 | length 265.9
  Top Layer w8: U1.33 888.17,976.37 919,945.55 989,945.55 1000.69,957.24 U2.4
RF430_SCK: U1.28 U2.10 | length 239.3
  Top Layer w8: U1.28 916.6,877.95 975.1,819.45 U2.10
SBWTCK: J2.3 U1.22 U6.1 | length 1014.4
  Top Layer w8: v1(218,745.55) 218,808.81 204.55,822.26 204.55,947.12 J2.3@244.34,986.9 ; v1@400.55,610.69 434.41,644.55 v1(453,644.55) ; U6.1@649,605.24 v1(649,659.55) 649,718.77 660.77,730.55 699,730.55 734.59,766.14 U1.22
  Bottom Layer w8: v1@218,745.69 263.86,745.69 v1(400,609.55) ; v1@454.55,645.69 468.41,659.55 v1(649,659.55)
SBWTDIO: C11.1 J2.4 R5.1 U1.23 U5.1 | length 937.2
  Top Layer w8: C11.1@597.94,555.69 R5.1@651.93,555.69 ; C11.1@597.94,558.08 U5.1@597.94,601.69 ; U5.1@599,603.24 v1(599,716.55) ; v1(739,735.55) 754.27,750.82 U1.23
  Bottom Layer w8: J2.4 309.55,934.69 328.55,915.69 ; 326.98,918.69 476,769.67 476,692.44 488.89,679.55 507.11,679.55 542.25,714.69 v1@598.55,714.69 ; v1@599,718.77 615.77,735.55 v1(739,735.55)
TMP_ALERT: R6.1 U1.9 U3.3 | length 1782
  Top Layer w8: U1.9 386.95,877.95 339.55,830.55 340.55,516.69 602.39,258.41 1040.55,258.41 1055.93,273.79 R6.1 961.34,316.69 952.46,325.56 802.44,325.56 802.44,367.74 841.02,406.33 U3.3
VCC: BT1.1 C2.1 C3.1 C6.1 C7.1 C8.1 D1.1 D2.1 J2.2 R5.2 U1.37 U1.48 | length 4091.9
  Top Layer w8: C3.1 v1(437.5,1225.04) ; C2.1@455.24,1123.69 C2.1@455.55,1123.69 ; C2.1@458.95,1122.69 481.9,1099.74 518.71,1099.74 U1.48 ; v1(670.55,510.69) 699.17,539.31 R5.2@699.17,555.69 ; C7.1 v1(780.49,1212.04)
  Top Layer w10: J2.2 280.55,1034.69 369.41,1123.55 C2.1 455.24,1123.69 449,1129.93 449,1162.05 C3.1@439,1172.05 ; R5.2@699.17,555.69 727.55,555.69 737.69,545.55 807.9,545.55 C8.1@834,571.65 ; U1.37 773.96,1101.89 C6.1 782.62,1158.42 C7.1 ; v1(1001,1213.55) 1001,1283.14 D2.1@1022.55,1304.69 ; D2.1 D1.1@1104.01,1305.23
  Top Layer w15: J2.2 208.55,1034.69 175.55,1001.69 175.55,546.69 517.2,205.04 v1(603.09,205.04) 1137.09,205.04 BT1.1@1646.04,205.04
  Bottom Layer w8: v1(603.09,205.04) 605.55,447.1 v1(670.55,510.69)
  Bottom Layer w10: v1@438.55,1225.69 468.61,1225.69 490.97,1248.04 744.49,1248.04 v1(780.49,1212.04) 1000.9,1212.04 v1@1000.9,1212.34 ; v1@1000.35,1212.89 v1(1001,1213.55)
pads on no net: *1.0 FID1.1 FID2.1 FID3.1 U1.1 U1.2 U1.3 U1.4 U1.5 U1.6 U1.7 U1.11 U1.12 U1.13 U1.14 U1.15 U1.16 U1.17 U1.18 U1.19 U1.29 U1.30 U1.38 U1.39 U1.40 U1.42 U1.43 U8.C2

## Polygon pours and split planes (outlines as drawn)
GND on Bottom Layer "Bottom Layer-No Net" (solid, remove dead copper, pour order 26): 330.55,1348.69 1270.55,1348.69 1270.55,288.69 330.55,288.69 330.55,1348.69
GND on Bottom Layer "Bottom Layer- GND" (solid, remove dead copper, pour order 6): 527.14,509.48 791.23,509.48 864.59,585.12 864.59,726.31 879.26,741.44 1021.08,741.44 1089.55,812.03 1089.55,1205.34 1065.1,1230.55 1045.54,1230.55 996.63,1180.12 766.77,1180.12 722.76,1225.51 561.37,1225.51 473.34,1134.74 473.34,781.77 444,751.52 444,595.21

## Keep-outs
Keep-Out Layer:
  lines w10: -5,3450 cw(c0,3450) 0,3455 ccw(c0,3450) -5,3450 ; 0,0 2335,0 2335,1723 0,1723 0,0 ; 4950,-5 ccw(c4950,0) 4955,0 cw(c4950,0) 4950,-5 ; 4950,3455 cw(c4950,3450) 4955,3450 ccw(c4950,3450) 4950,3455
  text ".Layer_Name" at 577,-858.49 h60

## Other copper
Top Layer:
  text ".Layer_Name" at 577,-858.49 h60
Bottom Layer:
  pour cut-out: 800.55,416.69 800.55,396.69 930.55,396.69 930.55,416.69
  pour cut-out: 791.5,404.5 791.5,524.5 771.5,524.5 771.5,404.5
  pour cut-out: 960.55,396.69 960.55,516.69 940.55,516.69 940.55,396.69
  pour cut-out: 940.55,516.69 800.55,516.69 800.55,496.69 940.55,496.69
  text ".Layer_Name" at 577,-858.49 h60

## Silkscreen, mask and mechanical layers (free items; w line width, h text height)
Top Overlay:
  circle w7: c501,1065.55 r3
  circle w7: c1106,1045.55 r3
  text "TIDA-00524A" at 309,1545 h30
  text "NFC-DATALOGGER-EVM" at 309,1475 h30
  text ".Layer_Name" at 577,-858.49 h60
Bottom Overlay:
  text ".Layer_Name" at 577,-858.49 h60
Top Paste:
  text ".Layer_Name" at 577,-858.49 h60
Bottom Paste:
  text ".Layer_Name" at 577,-858.49 h60
Top Solder:
  text ".Layer_Name" at 577,-858.49 h60
  text ".Layer_Name" at 577,-858.49 h60
Bottom Solder:
  text ".Layer_Name" at 577,-858.49 h60
Drill Guide:
  text ".Layer_Name" at 577,-858.49 h60
M1 Board Outline:
  the board outline again, w10
  text ".Layer_Name" at 577,-858.49 h60
M2 Board Dimensions:
  rectangle: 125,-400 500,-275
  rectangle: 0,-275 125,-150
  lines w7: 0,-275 1000,-275 ; 125,-400 125,-150 ; 250,-400 250,-150 ; 500,-400 500,-150 ; 750,-400 750,-150 ; 0,-400 0,-150 1000,-150 1000,-400 0,-400
  text ".Layer_Name" at 577,-858.49 h60
M3 3D STEP Top:
  text ".Layer_Name" at 577,-858.49 h60
M4 3D STEP Bottom:
  text ".Layer_Name" at 577,-858.49 h60
M5 Assembly Top:
  lines w10: -292,-930.17 6308,-930.17 ; -292,-726.83 6310,-726.83 ; -292,-523.5 -292,-1133.5 3713,-1133.5 6310,-1133.5 6310,-523.5 -291.5,-523.5 -291.5,-1133.5 1284,-1133.5 ; 2173,-1133.5 2173,-523.5 ; 3440,-726.83 3440,-523.5 ; 4280,-726.83 4280,-523.5 ; 4902,-1140 4902,-937.17
  text "COMPONENTS MARKED 'DNP' SHOULD NOT BE POPULATED." at 1153.5,-318.5 h60
  text "ASSEMBLY VARIANT:" at 1153,-434 h60
  text ".VariantName" at 2189,-434 h60
  text "PCB VIEWED FROM TOP SIDE" at -228.5,-655.67 h60
  text "BOARD #:" at 2248,-655.67 h60
  text ".PRJ_Number" at 2793.5,-655.67 h60
  text "REV:" at 3638,-655.67 h60
  text ".PCB_Rev" at 3929.5,-655.67 h60
  text "SVN REV:" at 4476,-655.67 h60
  text ".VersionControl_RevNumber" at 4982,-655.67 h60
  text "TID #:" at 2248,-859 h60
  text ".TID" at 2793.5,-859 h60
  text "PLOT NAME =" at -228.5,-1064.34 h60
  text ".plot_File_Name" at 577,-1064.34 h60
  text "GENERATED    :" at 2250,-1064.34 h60
  text ".Print_Date" at 3119.5,-1064.34 h60
  text ".Print_Time" at 3848.5,-1064.34 h60
  text "TEXAS INSTRUMENTS" at 5113,-1064.34 h60
M6 Assembly Bottom:
  lines w10: -292.5,-727.33 6309.5,-727.33 ; -290.5,-930.67 6309.5,-930.67 ; 1115.5,-1140.5 1115.5,-937.67 ; 1737.5,-727.33 1737.5,-524 ; 2577.5,-727.33 2577.5,-524 ; 3844.5,-1134 3844.5,-524 ; 4733.5,-1134 6309,-1134 6309,-524 -292.5,-524 -292.5,-1134 2304.5,-1134 6309.5,-1134 6309.5,-524
  text "COMPONENTS MARKED 'DNP' SHOULD NOT BE POPULATED." at 6102,-318 h60
  text ".VariantName" at 5058,-434 h60
  text "ASSEMBLY VARIANT:" at 6097,-434 h60
  text ".VersionControl_RevNumber" at 1035.5,-656.17 h60
  text "SVN REV:" at 1541.5,-656.17 h60
  text ".PCB_Rev" at 2088,-656.17 h60
  text "REV:" at 2379.5,-656.17 h60
  text ".PRJ_Number" at 3224,-656.17 h60
  text "BOARD #:" at 3769.5,-656.17 h60
  text "PCB VIEWED FROM BOTTOM SIDE" at 6246,-656.17 h60
  text ".TID" at 3224,-859.5 h60
  text "TID #:" at 3769.5,-859.5 h60
  text "TEXAS INSTRUMENTS" at 904.5,-1064.84 h60
  text ".Print_Time" at 2169,-1064.84 h60
  text ".Print_Date" at 2898,-1064.84 h60
  text "GENERATED    :" at 3767.5,-1064.84 h60
  text ".plot_File_Name" at 5440.5,-1064.84 h60
  text "PLOT NAME =" at 6246,-1064.84 h60
M9 Title Sheet:
  drawing of 57 lines, arcs and shapes, not listed
  text "1" at 739.84,8036.5 h70
  text "2" at 3235.5,8036.5 h70
  text "3" at 5724.84,8036.5 h70
  text "4" at 8231.51,8036.5 h70
  text "5" at 10730.5,8036.5 h70
  text "6" at 13235.5,8036.5 h70
  text "A" at -416.5,6893.5 h70
  text "A" at 14383.5,6893.5 h70
  text "B" at -416.5,4513.5 h70
  text "B" at 14383.5,4513.5 h70
  text "C" at -416.5,2138.5 h70
  text "C" at 14383.5,2138.5 h70
  text "PROJECT TITLE:" at 11343.5,277.5 h45
  text ".PRJ_Title" at 11393.5,144.17 h70
  text "DESIGNED FOR:" at 11343.5,-23.5 h45
  text ".PRJ_Customer" at 11393.5,-163.5 h70
  text "D" at -416.5,-231.5 h70
  text "D" at 14383.5,-231.5 h70
  text "FILE NAME:" at 11343.5,-323.5 h45
  text ".PCB_File_Name_No_Path" at 11393.5,-443.5 h70
  text "Texas Instruments (TI) and/or its licensors do not warrant the accuracy or completeness of this specification" at 6374,-605.34 h45
  text "ENGINEER:" at 11343.5,-613.5 h45
  text "LAYOUT BY:" at 12848.5,-613.5 h45
  text "or any information contained therein. TI and/or its licensors do not warrant that this design will meet" at 6329.01,-718 h45
  text ".PRJ_Engineer" at 11393.5,-768.49 h70
  text ".PCB_Layout" at 12899,-768.49 h70
  text "the specifications, will be suitable for your application or fit for any particular purpose, or will operate in" at 6329.01,-830.67 h45
  text ".Layer_Name" at 577,-858.49 h60
  text "ALTIUM DESIGNER VERSION:" at 12848.5,-923.5 h45
  text "an implementation. TI and/or its licensors do not warrant that the design is production worthy. You should" at 6329.01,-943.33 h45
  text "completely validate and test your design implementation to confirm the system functionality for your application." at 6374,-1056 h45
  text ".print_Scale" at 11393.5,-1056.83 h70
  text ".Application_BuildNumber" at 12899,-1056.83 h70
  text "1" at 739.84,-1263.5 h70
  text "2" at 3235.5,-1263.5 h70
  text "3" at 5724.84,-1263.5 h70
  text "4" at 8231.51,-1263.5 h70
  text "5" at 10730.5,-1263.5 h70
  text "6" at 13235.5,-1263.5 h70
M10 Fab Notes:
  drawing of 189 lines, arcs and shapes, not listed
  text "DESIGN INFORMATION" at 12381.02,6028 h60
  text "MIN. TRACK WIDTH:" at 11736.46,5848 h60
  text "8" at 12832.7,5848 h60
  text "MIL" at 12987.46,5848 h60
  text "MIN. CLEARANCE:" at 11736.46,5716 h60
  text "0.2" at 12772.7,5716 h60
  text "mm" at 12987.46,5716 h60
  text "MIN. VIA PAD SIZE:" at 11736.46,5584 h60
  text "20" at 12802.71,5584 h60
  text "MIL" at 12987.46,5584 h60
  text "0.05mm (2MIL)" at 12431.46,5442.29 h60
  text "MINIMUM ANNULAR RING" at 11407.23,5438 h60
  text "EXTERNAL" at 13139.46,5438 h60
  text "PER" at 11607.23,5320 h60
  text "IPC-D-275 CLASS 2 LEVEL C" at 11827.23,5320 h60
  text "MIL, HOLES" at 13315.46,5207.71 h60
  text "+/-" at 12923,5207 h60
  text "+/-" at 13777,5207 h60
  text "REGISTRATION TOLERANCES:" at 11407.23,5202 h60
  text "METAL" at 12607,5202 h60
  text "5" at 13183.2,5202 h60
  text "3" at 14016.2,5202 h60
  text "MIL" at 14132.46,5202 h60
  text "+/-" at 13777,5089 h60
  text "HOLE SIZE TOLERANCE (UNLESS OTHERWISE SPECIFIED):" at 11407.23,5084 h60
  text "3" at 14016.2,5084 h60
  text "MIL" at 14132.46,5084 h60
  text "MATERIAL:" at 11332.46,4874.54 h60
  text "FR-4 High Tg" at 12318.9,4734.21 h60
  text "FR-408" at 11753.46,4725.64 h60
  text "OTHER" at 13241.46,4725.64 h60
  text "X" at 12164,4722 h60
  text "62 MIL (1.6mm) +/-10%" at 12073.56,4562.92 h60
  text "THICKNESS:" at 11407.23,4558.64 h60
  text "X" at 11945.4,4558.64 h60
  text "OTHER" at 13358.46,4558.64 h60
  text "TOLERANCE:" at 11407.23,4400.64 h60
  text "X" at 12246.53,4400.64 h60
  text "ANSI IPC-6012 TYPE 3 CLASS 2" at 12433.48,4400.64 h60
  text "OTHER +/-" at 12433.46,4244.64 h60
  text "BOW & TWIST:" at 11407.23,4087.64 h60
  text "X" at 12246.53,4087.64 h60
  text "ANSI IPC-6012 TYPE 3 CLASS 2" at 12433.48,4087.64 h60
  text "OTHER +/-" at 12433.46,3929.13 h60
  text "DRILLING:" at 11332.46,3790.64 h60
  text "REFERENCE:" at 11407.23,3673.64 h60
  text "X" at 12055.46,3673.64 h60
  text "AS SHOWN" at 12242.46,3673.64 h60
  text "X" at 12956.46,3673.64 h60
  text "NC_DRILL FILES" at 13093.46,3673.64 h60
  text "PTH MIN COPPER THICKNESS:" at 11407.23,3515.64 h60
  text "X" at 12757.46,3515.64 h60
  text "1MIL" at 12894.46,3515.64 h60
  text "OTHER" at 13391.46,3515.64 h60
  text "BOARD FINISH:" at 11332.46,3356.64 h60
  text "SILKSCREEN:" at 11487.68,3238.64 h60
  text "X" at 12436.46,3238.64 h60
  text "TOP" at 12562.46,3238.64 h60
  text "X" at 12946.46,3238.64 h60
  text "BOTTOM" at 13073.46,3238.64 h60
  text "SILKSCREEN COLOR:" at 11487.68,3071.64 h60
  text "X" at 12435.42,3071.64 h60
  text "WHITE" at 12562.46,3071.64 h60
  text "OTHER" at 13073.46,3071.64 h60
  text "X" at 12566.42,2912.44 h60
  text "GREEN" at 12693.46,2912.44 h60
  text "OTHER" at 13311.46,2912.44 h60
  text "SOLDER RESIST COLOR:" at 11487.68,2901.64 h60
  text "X" at 12566.42,2742.44 h60
  text "MATTE" at 12693.46,2742.44 h60
  text "SEMI-GLOSS" at 13311,2741.8 h60
  text "IMMERSION GOLD (ENIG)" at 12393.46,2553.92 h60
  text "ENEPIG" at 13731,2550.64 h60
  text "SURFACE FINISH:" at 11332.46,2549.64 h60
  text "X" at 12206.51,2549.64 h60
  text "IMM. TIN/SILVER OR EQUIV" at 11662,2392.64 h60
  text "OTHER" at 13093.46,2392.64 h60
  text "ARRAY/PANEL:" at 11332.46,2213.64 h60
  text "CUT AND TRIM PER M1 BOARD OUTLINE" at 12393.46,2209.35 h60
  text "N.C. ROUTE" at 12393.46,2057.64 h60
  text "X" at 13072.46,2057.64 h60
  text "V. SCORE" at 13259.46,2057.64 h60
  text "CERTIFICATION:" at 11332.46,1920.64 h60
  text "MATERIALS AND WORKMANSHIP FOR ALL PCBS" at 12057.46,1920.64 h60
  text "TO MEET OR EXCEED THE REQUIREMENTS OF:" at 12057.46,1822.64 h60
  text "X" at 11683.96,1686.13 h60
  text "ANSI IPC-A-600F CLASS ->" at 11822.96,1686.13 h60
  text "X" at 13462.02,1686.13 h60
  text "2" at 13580.96,1686.14 h60
  text "1" at 13265.96,1684.64 h60
  text "3" at 13934.96,1684.64 h60
  text "X" at 11686.02,1526.64 h60
  text "UL 94V-0" at 11822.96,1526.64 h60
  text "X" at 12498.02,1526.64 h60
  text "RoHS" at 12634.96,1526.64 h60
  text "OTHER" at 13279.36,1526.64 h60
  text "PER ORDER" at 13676.42,1526.64 h60
  text "ADDITIONAL REQUIREMENTS:" at 11332.46,1385.64 h60
  text "MICROSECTION:" at 11407.23,1270.64 h60
  text "YES" at 12312.96,1270.64 h60
  text "REQUIRED" at 13174.46,1114.49 h60
  text "BARE BOARD ELEC. TEST:" at 11407.23,1111.64 h60
  text "NONE" at 12712.96,1111.64 h60
  text "X" at 13047.46,1111.64 h60
  text "PER ORDER" at 13766.46,1111.64 h60
  text "MANUFACTURER'S UL:" at 11407.23,954.64 h60
  text "RAIL" at 12572.96,950.35 h60
  text "METAL" at 13064.77,950.35 h60
  text "X" at 13440,950 h60
  text "SILK" at 13576.46,950.35 h60
  text ".Layer_Name" at 577,-858.49 h60
M11 Gerber Information:
  lines w10: -292,-930.17 6308,-930.17 ; -292,-726.83 6310,-726.83 ; -292,-523.5 -292,-1133.5 3713,-1133.5 6310,-1133.5 6310,-523.5 -291.5,-523.5 -291.5,-1133.5 1284,-1133.5 ; 2173,-1133.5 2173,-523.5 ; 3440,-726.83 3440,-523.5 ; 4280,-726.83 4280,-523.5 ; 4902,-1140 4902,-937.17
  text "ALL ARTWORK VIEWED FROM TOP SIDE" at -228.5,-655.67 h60
  text "BOARD #:" at 2248,-655.67 h60
  text ".PRJ_Number" at 2793.5,-655.67 h60
  text "REV:" at 3638,-655.67 h60
  text ".PCB_Rev" at 3929.5,-655.67 h60
  text "SVN REV:" at 4476,-655.67 h60
  text ".VersionControl_RevNumber" at 4982,-655.67 h60
  text "LAYER NAME =" at -228.5,-858.49 h60
  text "TID #:" at 2248,-859 h60
  text ".TID" at 2793.5,-859 h60
  text "PLOT NAME =" at -228.5,-1064.34 h60
  text ".plot_File_Name" at 577,-1064.34 h60
  text "GENERATED    :" at 2250,-1064.34 h60
  text ".Print_Date" at 3119.5,-1064.34 h60
  text ".Print_Time" at 3848.5,-1064.34 h60
  text "TEXAS INSTRUMENTS" at 5113,-1064.34 h60
M12 Stackup:
  drawing of 191 lines, arcs and shapes, not listed
  text "Layer" at 9790.34,7830 h60
  text "Name" at 10200.26,7830 h60
  text "Material" at 11130,7830 h60
  text "Thickness" at 11989.77,7830 h60
  text "Constant" at 12639.6,7830 h60
  text "Board Layer Stack" at 13209.46,7830 h60
  text "1" at 9790.34,7710 h60
  text "Top Overlay" at 10200.26,7710 h60
  text "2" at 9790.34,7590 h60
  text "Top Solder" at 10200.26,7590 h60
  text "Solder Resist" at 11130,7590 h60
  text "0.40mil" at 11989.77,7590 h60
  text "3.5" at 12639.6,7590 h60
  text "3" at 9790.34,7470 h60
  text "Top Layer" at 10200.26,7470 h60
  text "Copper" at 11130,7470 h60
  text "1.40mil" at 11989.77,7470 h60
  text "4" at 9790.34,7350 h60
  text "Dielectric1" at 10200.26,7350 h60
  text "FR-4" at 11130,7350 h60
  text "59.20mil" at 11989.77,7350 h60
  text "4.8" at 12639.6,7350 h60
  text "5" at 9790.34,7230 h60
  text "Bottom Layer" at 10200.26,7230 h60
  text "Copper" at 11130,7230 h60
  text "1.40mil" at 11989.77,7230 h60
  text "6" at 9790.34,7110 h60
  text "Bottom Solder" at 10200.26,7110 h60
  text "Solder Resist" at 11130,7110 h60
  text "0.40mil" at 11989.77,7110 h60
  text "3.5" at 12639.6,7110 h60
  text "7" at 9790.34,6990 h60
  text "Bottom Overlay" at 10200.26,6990 h60
  text ".Layer_Name" at 577,-858.49 h60
M13 Component Bodies Top:
  text ".Layer_Name" at 577,-858.49 h60
M14 Component Bodies Bottom:
  text ".Layer_Name" at 577,-858.49 h60
M15 Courtyards Top:
  text ".Layer_Name" at 577,-858.49 h60
M16 Courtyards Bottom:
  text ".Layer_Name" at 577,-858.49 h60
Drill Drawing:
  circle w10: c3784.62,1458 r15
  circle w10: c3784.62,1458 r25
  circle w10: c3784.62,408 r25
  lines w10: 3759.62,283 3809.62,283 3784.62,233 3759.62,283 ; 3759.62,533 3784.62,545.5 3809.62,533 3797.12,558 3809.62,583 3784.62,570.5 3759.62,583 3772.12,558 3759.62,533 ; 3759.62,695.5 3772.12,695.5 3784.62,683 3797.12,695.5 3809.62,695.5 3797.12,708 3809.62,720.5 3797.12,720.5 3784.62,733 3772.12,720.5 3759.62,720.5 3772.12,708 3759.62,695.5 ; 3759.62,833 3759.62,845.5 3772.12,858 3759.62,870.5 3759.62,883 3772.12,883 3784.62,870.5 3797.12,883 3809.62,883 3809.62,870.5 3797.12,858 3809.62,845.5 3809.62,833 3797.12,833 3784.62,845.5 3772.12,833 3759.62,833 ; 3759.62,995.5 3772.12,995.5 3772.12,983 3797.12,983 3797.12,995.5 3809.62,995.5 3809.62,1020.5 3797.12,1020.5 3797.12,1033 3772.12,1033 3772.12,1020.5 3759.62,1020.5 3759.62,995.5 ; 3759.62,1158 3784.62,1133 3809.62,1158 3784.62,1183 3759.62,1158 ; 3759.62,1283 3809.62,1283 3809.62,1333 3759.62,1333 3759.62,1283 ; 3769.62,700.5 3777.12,700.5 3784.62,693 3792.12,700.5 3799.62,700.5 3792.12,708 3799.62,715.5 3792.12,715.5 3784.62,723 3777.12,715.5 3769.62,715.5 3777.12,708 3769.62,700.5
  lines w15: 3691.5,188 7570.47,188 ; 3691.5,1538 7570.47,1538 ; 4242.38,38 4242.38,1688 ; 4940.19,38 4940.19,1688 ; 6285.79,38 6285.79,1688 ; 6791.67,38 6791.67,1688 ; 3691.5,38 7570.47,38 7570.47,1688 3691.5,1688 3691.5,38
  text "Symbol" at 3781.5,1583 h72
  text "Hit Count" at 4287.38,1583 h72
  text "Finished Hole Size" at 4985.19,1583 h72
  text "Plated" at 6330.79,1583 h72
  text "Hole Type" at 6836.67,1583 h72
  text "1" at 4287.38,1433 h60
  text "8.00mil (0.203mm)" at 4985.19,1433 h60
  text "PTH" at 6330.79,1433 h60
  text "Round" at 6836.67,1433 h60
  text "1" at 4287.38,1283 h60
  text "12.00mil (0.305mm)" at 4985.19,1283 h60
  text "PTH" at 6330.79,1283 h60
  text "Round" at 6836.67,1283 h60
  text "1" at 4287.38,1133 h60
  text "31.00mil (0.787mm)" at 4985.19,1133 h60
  text "NPTH" at 6330.79,1133 h60
  text "Slot" at 6836.67,1133 h60
  text "2" at 4287.38,983 h60
  text "28.00mil (0.711mm)" at 4985.19,983 h60
  text "PTH" at 6330.79,983 h60
  text "Round" at 6836.67,983 h60
  text "2" at 4287.38,833 h60
  text "30.00mil (0.762mm)" at 4985.19,833 h60
  text "PTH" at 6330.79,833 h60
  text "Round" at 6836.67,833 h60
  text "2" at 4287.38,683 h60
  text "31.00mil (0.787mm)" at 4985.19,683 h60
  text "NPTH" at 6330.79,683 h60
  text "Slot" at 6836.67,683 h60
  text "6" at 4287.38,533 h60
  text "26.00mil (0.660mm)" at 4985.19,533 h60
  text "PTH" at 6330.79,533 h60
  text "Round" at 6836.67,533 h60
  text "9" at 4287.38,383 h60
  text "7.87mil (0.200mm)" at 4985.19,383 h60
  text "PTH" at 6330.79,383 h60
  text "Round" at 6836.67,383 h60
  text "49" at 4287.38,233 h60
  text "10.00mil (0.254mm)" at 4985.19,233 h60
  text "PTH" at 6330.79,233 h60
  text "Round" at 6836.67,233 h60
  text "73 Total" at 4287.38,83 h60
  text ".Layer_Name" at 577,-858.49 h60

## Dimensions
0,0 to 2335,0 on M2 Board Dimensions
0,0 to 0,1723 on M2 Board Dimensions
0,-400 to 1000,-400 on M2 Board Dimensions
